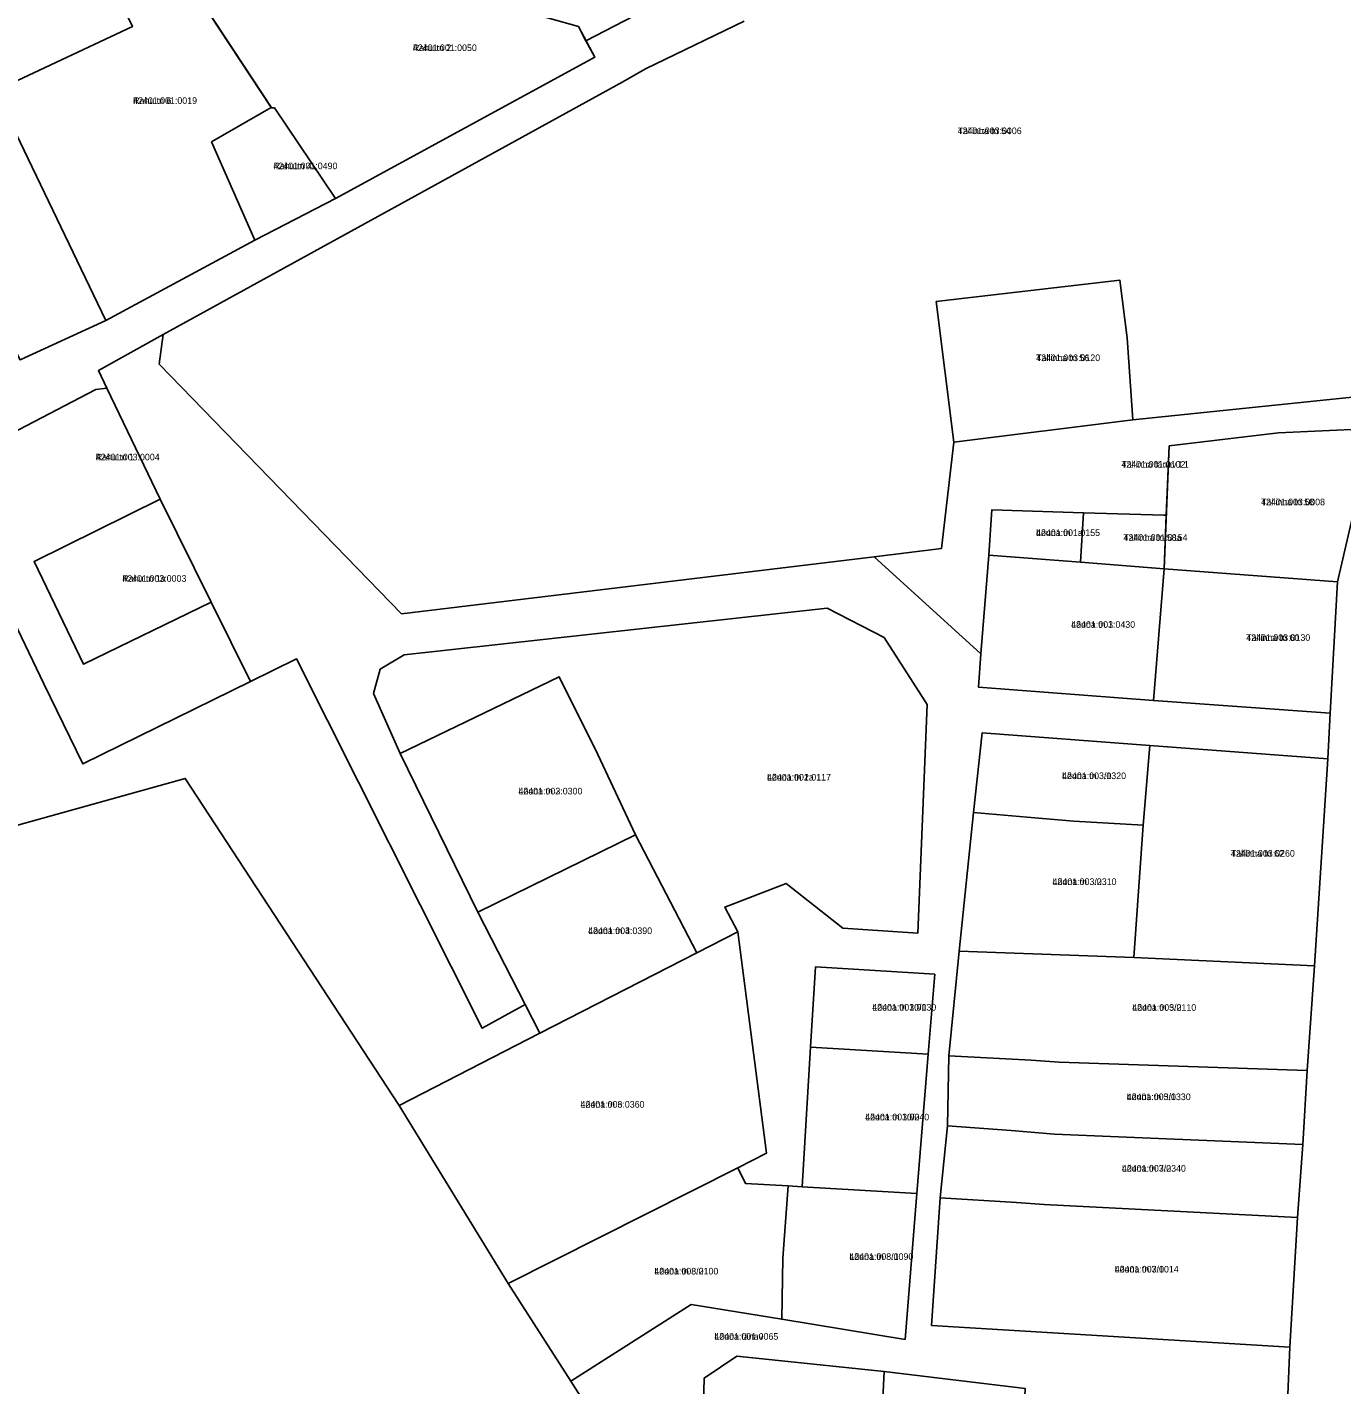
# Model space of a CAD drawing. Extents: x 595979 to 597983, y 6604231 to 6607350.
# Drawn here: x 597176.2 to 597474.2, y 6605161.4 to 6605469.2 of the extents above; entities that cross this region are included whole.
import ezdxf

# ---------------------------------------------------------------- set-up
doc = ezdxf.new("R2010")
doc.units = 0
for name, color, linetype in [('L_AADRESS', 7, 'Continuous'), ('PIIR', 7, 'Continuous'), ('TUNNUS', 7, 'Continuous')]:
    doc.layers.add(name, color=color, linetype=linetype)

msp = doc.modelspace()

# ---------------------------------------------------------------- linework, layer by layer
at = {"layer": 'PIIR'}
for points in [[(597487.25, 6605511.01), (597483.61, 6605418.8), (597480.24, 6605385.69), (597426.8, 6605380.15), (597425.53, 6605398.77), (597423.84, 6605411.85), (597382.25, 6605406.98), (597386.22, 6605375.09), (597383.41, 6605350.97), (597368.21, 6605349.13), (597261.05, 6605336.16), (597206.07, 6605392.81), (597206.99, 6605399.53), (597311.2, 6605456.81), (597316.36, 6605459.7), (597338.73, 6605470.54)], [(597491.74, 6604767.94), (597460.13, 6604897.15), (597453.23, 6604975.44), (597460.84, 6605133.45), (597461.82, 6605155.54), (597462.44, 6605169.92), (597464.18, 6605199.35), (597465.36, 6605215.89), (597466.32, 6605232.67), (597467.99, 6605256.4), (597471.01, 6605303.31), (597471.58, 6605313.69), (597473.22, 6605343.42), (597478.52, 6605366.25), (597479.63, 6605378.15), (597480.24, 6605385.69), (597483.61, 6605418.8), (597487.25, 6605511.01)], [(597153.75, 6605485.48), (597168.9, 6605454.75), (597194, 6605402.66), (597174.6, 6605393.75), (597156.46, 6605429.19), (597153.55, 6605434.58), (597138.08, 6605467.03), (597120.14, 6605502.12)], [(597174.6, 6605393.75), (597194, 6605402.66), (597227.8, 6605420.87), (597246.04, 6605430.3), (597304.83, 6605462.35), (597302.84, 6605466.06), (597324.71, 6605477.46)], [(597324.71, 6605477.46), (597302.84, 6605466.06), (597301.12, 6605469.32)], [(597338.73, 6605470.54), (597316.36, 6605459.7), (597311.2, 6605456.81), (597206.99, 6605399.53), (597192.31, 6605391.34), (597194.24, 6605387.32), (597191.72, 6605387.01), (597156.63, 6605368.74)], [(597321.77, 6605127.05), (597299.38, 6605162.18), (597326.72, 6605179.6), (597347.23, 6605176.24), (597375.19, 6605171.67), (597377.88, 6605204.79), (597380.45, 6605236.34), (597381.92, 6605254.47), (597354.86, 6605256.11), (597353.75, 6605237.96), (597351.82, 6605206.3), (597348.67, 6605206.49), (597338.98, 6605207.04), (597337.28, 6605210.61), (597343.77, 6605213.88), (597337.28, 6605264.1), (597334.29, 6605269.71), (597348.23, 6605275.06), (597361.07, 6605264.88), (597378.1, 6605263.79), (597380.18, 6605315.61), (597370.45, 6605330.81), (597357.51, 6605337.43), (597261.64, 6605326.88), (597256.16, 6605323.62), (597254.71, 6605318.15), (597260.76, 6605304.49), (597278.36, 6605268.55), (597289.05, 6605247.62), (597279.35, 6605242.24), (597237.24, 6605325.94), (597226.8, 6605320.8), (597217.87, 6605338.8), (597206.34, 6605362.14), (597194.24, 6605387.32), (597192.31, 6605391.34), (597206.99, 6605399.53), (597206.07, 6605392.81), (597261.05, 6605336.16), (597368.21, 6605349.13), (597392.39, 6605327.14), (597391.82, 6605319.57), (597431.49, 6605316.52), (597471.58, 6605313.69), (597471.01, 6605303.31), (597430.65, 6605306.35), (597392.64, 6605309.18), (597390.73, 6605291.12), (597387.45, 6605259.69), (597385.07, 6605235.96), (597384.83, 6605220.07), (597383.15, 6605203.78), (597381.19, 6605174.85), (597462.44, 6605169.92), (597461.82, 6605155.54)], [(597174.03, 6605332.6), (597179.96, 6605320.31), (597188.79, 6605302.16), (597226.8, 6605320.8), (597237.24, 6605325.94), (597279.35, 6605242.24), (597289.05, 6605247.62), (597292.41, 6605241.09), (597260.5, 6605224.72), (597211.99, 6605298.86), (597070.11, 6605259.35)], [(597402.38, 6605160.58), (597370.47, 6605164.38), (597337.07, 6605167.91), (597329.67, 6605162.91), (597328.4, 6605116.18)]]:
    msp.add_lwpolyline(points, dxfattribs=at)
for points in [[(597185.05, 6605500.54), (597200.03, 6605469.31), (597168.9, 6605454.75), (597153.75, 6605485.48)], [(597185.05, 6605500.54), (597200.9, 6605497.42), (597231.46, 6605450.99), (597217.98, 6605443.18), (597227.8, 6605420.87), (597194, 6605402.66), (597168.9, 6605454.75), (597200.03, 6605469.31)], [(597232.23, 6605450.89), (597231.64, 6605450.82), (597201.09, 6605497.22), (597248.64, 6605490.2), (597252.5, 6605488.75), (597262.8, 6605480.17), (597301.12, 6605469.32), (597304.83, 6605462.35), (597246.04, 6605430.3)], [(597231.46, 6605450.99), (597232.23, 6605450.89), (597246.04, 6605430.3), (597227.8, 6605420.87), (597217.98, 6605443.18)], [(597426.8, 6605380.15), (597386.22, 6605375.09), (597382.25, 6605406.98), (597423.84, 6605411.85), (597425.53, 6605398.77)], [(597191.72, 6605387.01), (597194.24, 6605387.32), (597206.34, 6605362.14), (597177.74, 6605348.02), (597188.94, 6605324.73), (597217.87, 6605338.8), (597226.8, 6605320.8), (597188.79, 6605302.16), (597179.96, 6605320.31), (597174.03, 6605332.6), (597156.63, 6605368.74)], [(597459.86, 6605377.24), (597435.08, 6605374.23), (597434.39, 6605358.51), (597433.85, 6605358.52), (597415.66, 6605359.08), (597394.83, 6605359.72), (597394.16, 6605349.5), (597392.39, 6605327.14), (597368.21, 6605349.13), (597383.41, 6605350.97), (597386.22, 6605375.09), (597426.8, 6605380.15), (597480.24, 6605385.69), (597479.63, 6605378.15)], [(597435.08, 6605374.23), (597459.86, 6605377.24), (597479.63, 6605378.15), (597478.52, 6605366.25), (597473.22, 6605343.42), (597433.89, 6605346.38)], [(597206.34, 6605362.14), (597217.87, 6605338.8), (597188.94, 6605324.73), (597177.74, 6605348.02)], [(597414.94, 6605347.92), (597394.16, 6605349.5), (597394.83, 6605359.72), (597415.66, 6605359.08)], [(597414.94, 6605347.92), (597415.66, 6605359.08), (597433.85, 6605358.52), (597434.39, 6605358.51), (597433.89, 6605346.38)], [(597391.82, 6605319.57), (597392.39, 6605327.14), (597394.16, 6605349.5), (597414.94, 6605347.92), (597433.89, 6605346.38), (597431.49, 6605316.52)], [(597433.89, 6605346.38), (597473.22, 6605343.42), (597471.58, 6605313.69), (597431.49, 6605316.52)], [(597337.28, 6605264.1), (597327.98, 6605259.33), (597314.1, 6605286.04), (597305.51, 6605304.28), (597296.8, 6605321.9), (597260.76, 6605304.49), (597254.71, 6605318.15), (597256.16, 6605323.62), (597261.64, 6605326.88), (597357.51, 6605337.43), (597370.45, 6605330.81), (597380.18, 6605315.61), (597378.1, 6605263.79), (597361.07, 6605264.88), (597348.23, 6605275.06), (597334.29, 6605269.71)], [(597296.8, 6605321.9), (597305.51, 6605304.28), (597314.1, 6605286.04), (597278.36, 6605268.55), (597260.76, 6605304.49)], [(597392.64, 6605309.18), (597430.65, 6605306.35), (597429.18, 6605288.24), (597413.46, 6605289.19), (597404.59, 6605289.95), (597390.73, 6605291.12)], [(597471.01, 6605303.31), (597467.99, 6605256.4), (597427.07, 6605258.27), (597429.18, 6605288.24), (597430.65, 6605306.35)], [(597070.11, 6605259.35), (597211.99, 6605298.86), (597260.5, 6605224.72), (597285.2, 6605184.34), (597299.38, 6605162.18), (597321.75, 6605127.1), (597316.32, 6605100.66), (597302.35, 6605090.93), (597218.27, 6605028.59), (597130.93, 6604964.61), (597074.78, 6605236.74)], [(597390.73, 6605291.12), (597404.59, 6605289.95), (597413.46, 6605289.19), (597429.18, 6605288.24), (597427.07, 6605258.27), (597387.45, 6605259.69)], [(597292.41, 6605241.09), (597289.05, 6605247.62), (597278.36, 6605268.55), (597314.1, 6605286.04), (597327.98, 6605259.33)], [(597260.5, 6605224.72), (597292.41, 6605241.09), (597327.98, 6605259.33), (597337.28, 6605264.1), (597343.77, 6605213.88), (597337.28, 6605210.61), (597285.2, 6605184.34)], [(597467.99, 6605256.4), (597466.32, 6605232.67), (597410.08, 6605234.56), (597403.77, 6605235.01), (597385.07, 6605235.96), (597387.45, 6605259.69), (597427.07, 6605258.27)], [(597380.45, 6605236.34), (597353.75, 6605237.96), (597354.86, 6605256.11), (597381.92, 6605254.47)], [(597353.75, 6605237.96), (597380.45, 6605236.34), (597377.88, 6605204.79), (597351.82, 6605206.3)], [(597385.07, 6605235.96), (597403.77, 6605235.01), (597410.08, 6605234.56), (597466.32, 6605232.67), (597465.36, 6605215.89), (597409.08, 6605218.19), (597399.27, 6605219.04), (597384.83, 6605220.07)], [(597384.83, 6605220.07), (597399.27, 6605219.04), (597409.08, 6605218.19), (597465.36, 6605215.89), (597464.18, 6605199.35), (597406.69, 6605202.25), (597400.44, 6605202.71), (597383.15, 6605203.78)], [(597285.2, 6605184.34), (597337.28, 6605210.61), (597338.98, 6605207.04), (597348.67, 6605206.49), (597347.51, 6605190.09), (597347.23, 6605176.24), (597326.72, 6605179.6), (597299.38, 6605162.18)], [(597347.51, 6605190.09), (597348.67, 6605206.49), (597351.82, 6605206.3), (597377.88, 6605204.79), (597375.19, 6605171.67), (597347.23, 6605176.24)], [(597383.15, 6605203.78), (597400.44, 6605202.71), (597406.69, 6605202.25), (597464.18, 6605199.35), (597462.44, 6605169.92), (597381.19, 6605174.85)], [(597370.47, 6605164.38), (597368.02, 6605114.71), (597328.4, 6605116.18), (597329.67, 6605162.91), (597337.07, 6605167.91)], [(597368.02, 6605114.71), (597370.47, 6605164.38), (597402.38, 6605160.58), (597400.65, 6605121.3)]]:
    msp.add_lwpolyline(points, close=True, dxfattribs=at)

# ---------------------------------------------------------------- texts
at = {"layer": 'L_AADRESS'}
for s, p in [('Rahu tn 2', (597263.6, 6605463.76)), ('Rahu tn 6', (597200.18, 6605451.78)), ('Tallinna tn 54', (597387.11, 6605444.93)), ('Rahu tn 4', (597232.01, 6605436.98)), ('Tallinna tn 56', (597404.91, 6605393.47)), ('Rahu tn 1', (597191.71, 6605370.96)), ('Tallinna tänav L1', (597424.23, 6605369.32)), ('Tallinna tn 58', (597455.88, 6605360.79)), ('Lõuna tn 1a', (597404.88, 6605353.82)), ('Tallinna tn 58a', (597424.7, 6605352.73)), ('Rahu tn 1a', (597197.76, 6605343.44)), ('Lõuna tn 1', (597412.84, 6605333.01)), ('Tallinna tn 60', (597452.53, 6605330.04)), ('Lõuna tn 2a', (597343.89, 6605298.38)), ('Lõuna tn 3/1', (597410.78, 6605298.71)), ('Lõuna tn 2', (597287.54, 6605295.23)), ('Tallinna tn 62', (597449.04, 6605281.12)), ('Lõuna tn 3/2', (597408.62, 6605274.7)), ('Lõuna tn 4', (597303.34, 6605263.57)), ('Lõuna tn 10/1', (597367.75, 6605246.23)), ('Lõuna tn 5/2', (597426.68, 6605246.18)), ('Lõuna tn 5/1', (597425.43, 6605225.93)), ('Lõuna tn 6', (597301.62, 6605224.22)), ('Lõuna tn 10/2', (597366.14, 6605221.34)), ('Lõuna tn 7/2', (597424.34, 6605209.71)), ('Lõuna tn 8/1', (597362.55, 6605189.71)), ('Lõuna tn 8/2', (597318.35, 6605186.4)), ('Lõuna tn 7/1', (597422.72, 6605186.85)), ('Lõuna tänav', (597331.95, 6605171.6))]:
    msp.add_text(s, height=1.5, dxfattribs=at).set_placement(p)
at = {"layer": 'TUNNUS'}
for s, p in [('42401:001:0050', (597263.6, 6605463.76)), ('42401:001:0019', (597200.18, 6605451.78)), ('42401:003:0006', (597387.11, 6605444.93)), ('42401:001:0490', (597232.01, 6605436.98)), ('42401:003:0120', (597404.91, 6605393.47)), ('42401:003:0004', (597191.71, 6605370.96)), ('42401:001:0102', (597424.23, 6605369.32)), ('42401:003:0008', (597455.88, 6605360.79)), ('42401:001:0155', (597404.88, 6605353.82)), ('42401:001:0154', (597424.7, 6605352.73)), ('42401:003:0003', (597197.76, 6605343.44)), ('42401:003:0430', (597412.84, 6605333.01)), ('42401:003:0130', (597452.53, 6605330.04)), ('42401:001:0117', (597343.89, 6605298.38)), ('42401:003:0320', (597410.78, 6605298.71)), ('42401:003:0300', (597287.54, 6605295.23)), ('42401:003:0260', (597449.04, 6605281.12)), ('42401:003:0310', (597408.62, 6605274.7)), ('42401:003:0390', (597303.34, 6605263.57)), ('42401:003:0030', (597367.75, 6605246.23)), ('42401:003:0110', (597426.68, 6605246.18)), ('42401:003:0330', (597425.43, 6605225.93)), ('42401:003:0360', (597301.62, 6605224.22)), ('42401:003:0040', (597366.14, 6605221.34)), ('42401:003:0340', (597424.34, 6605209.71)), ('42401:003:0090', (597362.55, 6605189.71)), ('42401:003:0100', (597318.35, 6605186.4)), ('42401:003:0014', (597422.72, 6605186.85)), ('42401:001:0065', (597331.95, 6605171.6))]:
    msp.add_text(s, height=1.5, dxfattribs=at).set_placement(p)

doc.saveas('drawing.dxf')
